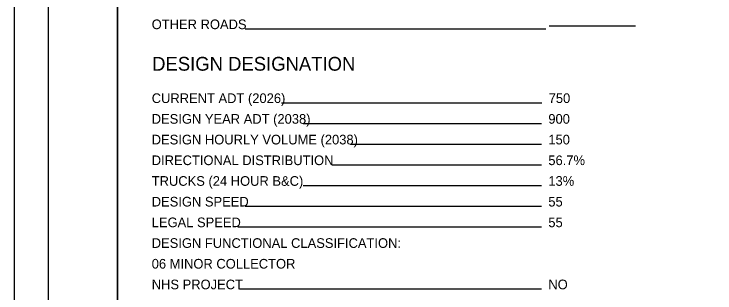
# Model space of a CAD drawing. Extents: x 0 to 34, y 0 to 22.
# Drawn here: x 0 to 10.15, y 7.05 to 11.1 of the extents above; entities that cross this region are included whole.
import ezdxf

# ---------------------------------------------------------------- set-up
doc = ezdxf.new("R2010")
doc.units = 0
for name, color, linetype in [('SH_Border', 7, 'Continuous'), ('SH_Cut_Line', 7, 'Continuous'), ('SH_Data', 7, 'Continuous'), ('SH_Text', 7, 'Continuous')]:
    doc.layers.add(name, color=color, linetype=linetype)

msp = doc.modelspace()

# ---------------------------------------------------------------- linework, layer by layer
at = {"layer": 'SH_Border'}
for points in [[(0.5, 21.5), (1.5, 21.5), (1.5, 0.5), (0.5, 0.5)], [(1.5, 21.5), (33.5, 21.5), (33.5, 0.5), (1.5, 0.5)]]:
    msp.add_lwpolyline(points, close=True, dxfattribs=at)
at = {"layer": 'SH_Cut_Line'}
msp.add_lwpolyline([(0, 0), (34, 0), (34, 22), (0, 22)], close=True, dxfattribs=at)
at = {"layer": 'SH_Data'}
for p, q in [((7.7, 10.877), (3.347, 10.877)), ((9, 10.922), (7.75, 10.922)), ((7.642, 9.806), (3.871, 9.806)), ((7.637, 9.506), (4.189, 9.506)), ((7.637, 9.206), (4.872, 9.206)), ((7.637, 8.906), (4.604, 8.906)), ((7.637, 8.606), (4.189, 8.606)), ((7.637, 8.306), (3.346, 8.306)), ((7.637, 8.006), (3.242, 8.006)), ((7.637, 7.106), (3.267, 7.106))]:
    msp.add_line(p, q, dxfattribs=at)

# ---------------------------------------------------------------- texts
msp.add_text('DESIGN DESIGNATION', height=0.2, dxfattribs=at).set_placement((2, 10.275))
at = {"layer": 'SH_Text'}
for s, p in [('OTHER ROADS', (1.994, 10.877)), ('CURRENT ADT (2026)', (1.994, 9.806)), ('750', (7.742, 9.806)), ('DESIGN YEAR ADT (2038)', (1.994, 9.506)), ('900', (7.737, 9.506)), ('DESIGN HOURLY VOLUME (2038)', (1.994, 9.206)), ('150', (7.737, 9.206)), ('DIRECTIONAL DISTRIBUTION', (1.994, 8.906)), ('56.7%', (7.737, 8.906)), ('TRUCKS (24 HOUR B&C)', (1.994, 8.606)), ('13%', (7.737, 8.606)), ('DESIGN SPEED', (1.994, 8.306)), ('55', (7.737, 8.306)), ('LEGAL SPEED', (1.994, 8.006)), ('55', (7.737, 8.006)), ('DESIGN FUNCTIONAL CLASSIFICATION:', (1.994, 7.706)), ('06 MINOR COLLECTOR', (1.994, 7.406)), ('NHS PROJECT', (1.994, 7.106)), ('NO', (7.737, 7.106))]:
    msp.add_text(s, height=0.14, dxfattribs=at).set_placement(p)

doc.saveas('drawing.dxf')
